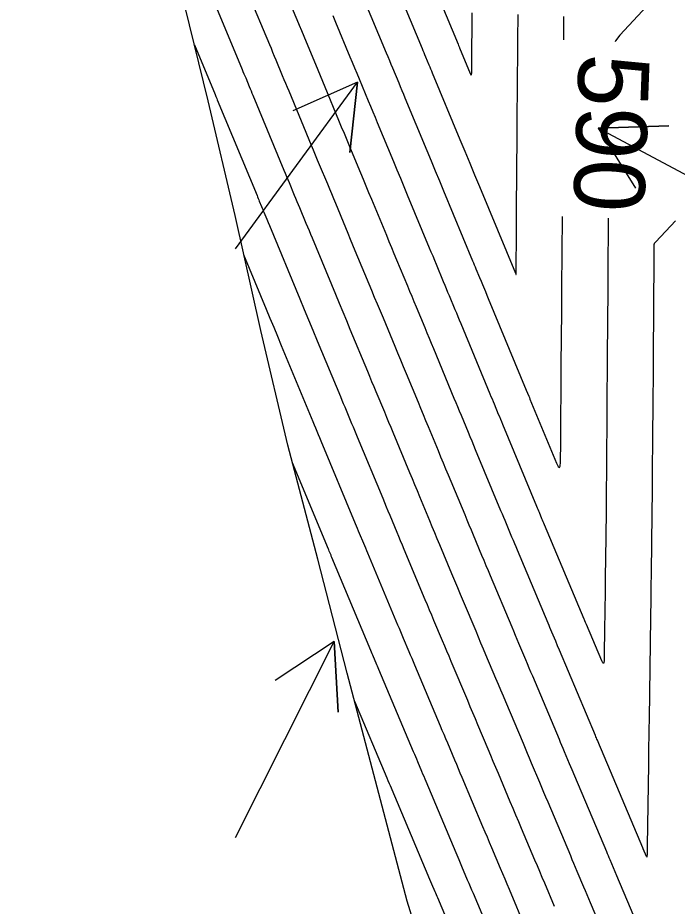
# Model space of a CAD drawing. Extents: x 954385 to 988206, y 1868364 to 1924553.
# Drawn here: x 957938.6 to 957994.6, y 1918863.1 to 1918938.6 of the extents above; entities that cross this region are included whole.
import ezdxf

# ---------------------------------------------------------------- set-up
doc = ezdxf.new("R2010")
doc.units = 0
for name, color, linetype in [('24', 7, 'Continuous'), ('26', 7, 'Continuous'), ('5', 7, 'Continuous'), ('6', 7, 'Continuous'), ('7', 7, 'Continuous')]:
    doc.layers.add(name, color=color, linetype=linetype)

msp = doc.modelspace()

# ---------------------------------------------------------------- linework, layer by layer
at = {"layer": '24'}
msp.add_lwpolyline([(957974.671, 1918853.956), (957971.691, 1918863.536), (957969.153, 1918873.215), (957966.605, 1918882.892), (957964.105, 1918892.58), (957961.58, 1918902.262), (957959.271, 1918911.992), (957957.104, 1918921.755), (957954.809, 1918931.489), (957952.428, 1918941.203), (957950.425, 1918951.002), (957949.07, 1918960.947), (957947.365, 1918970.813), (957946.225, 1918980.806), (957947.369, 1918991.311), (957948.976, 1919001.92), (957947.688, 1919008.805), (957946.681, 1919011.654), (957944.248, 1919021.357), (957948.184, 1919032.489), (957949.869, 1919043.116), (957945.982, 1919052.492), (957942.292, 1919061.913), (957938.649, 1919071.344)], dxfattribs=at)
at = {"layer": '26'}
for points in [[(957957.131, 1918918.928), (957967.485, 1918933.074), (957966.837, 1918927.109), (957967.485, 1918933.074), (957961.996, 1918930.653)], [(958007.131, 1918918.928), (957987.907, 1918929.179), (957993.904, 1918929.381), (957987.907, 1918929.179), (957991.081, 1918924.086)], [(957957.131, 1918868.928), (957965.513, 1918885.566), (957965.855, 1918879.576), (957965.513, 1918885.566), (957960.496, 1918882.276)]]:
    msp.add_lwpolyline(points, dxfattribs=at)
at = {"layer": '6'}
for points in [[(957992.035, 1918939.534), (957989.765, 1918937.088), (957989.381, 1918936.594), (957989.344, 1918936.521)], [(957988.775, 1918921.532), (957988.739, 1918916.732), (957988.736, 1918916.42), (957988.734, 1918916.107), (957988.731, 1918915.794), (957988.729, 1918915.482), (957988.686, 1918909.856), (957988.683, 1918909.443), (957988.678, 1918908.883), (957988.677, 1918908.703), (957988.675, 1918908.402), (957988.673, 1918908.222), (957988.664, 1918906.986), (957988.661, 1918906.534), (957988.658, 1918906.081), (957988.611, 1918899.574), (957988.605, 1918898.825), (957988.598, 1918898.077), (957988.591, 1918897.328), (957988.582, 1918896.58), (957988.532, 1918892.58), (957988.526, 1918892.09), (957988.52, 1918891.6), (957988.507, 1918890.619), (957988.504, 1918890.374), (957988.501, 1918890.129), (957988.498, 1918889.884), (957988.495, 1918889.638), (957988.479, 1918888.381), (957988.475, 1918888.09), (957988.472, 1918887.799), (957988.468, 1918887.508), (957988.463, 1918887.216), (957988.445, 1918885.933), (957988.441, 1918885.687), (957988.438, 1918885.441), (957988.434, 1918885.195), (957988.43, 1918884.949), (957988.416, 1918883.965), (957988.401, 1918883.778), (957988.363, 1918883.71), (957988.302, 1918883.759), (957988.218, 1918883.927), (957986.914, 1918887.025), (957986.848, 1918887.18), (957986.783, 1918887.335), (957986.75, 1918887.412), (957986.718, 1918887.49), (957983.36, 1918895.498), (957983.306, 1918895.627), (957983.253, 1918895.755), (957983.199, 1918895.883), (957983.145, 1918896.011), (957982.93, 1918896.524), (957982.877, 1918896.652), (957982.823, 1918896.78), (957982.77, 1918896.909), (957982.716, 1918897.037), (957979.821, 1918904.019), (957979.733, 1918904.233), (957979.644, 1918904.447), (957979.555, 1918904.661), (957979.467, 1918904.874), (957979.112, 1918905.729), (957979.023, 1918905.943), (957978.934, 1918906.156), (957978.846, 1918906.37), (957978.757, 1918906.584), (957976.274, 1918912.567), (957976.151, 1918912.864), (957976.028, 1918913.16), (957975.905, 1918913.457), (957975.782, 1918913.753), (957975.29, 1918914.939), (957975.167, 1918915.235), (957975.044, 1918915.532), (957974.921, 1918915.828), (957974.798, 1918916.124), (957974.183, 1918917.605), (957974.04, 1918917.951), (957973.896, 1918918.296), (957973.753, 1918918.642), (957973.609, 1918918.988), (957971.739, 1918923.496), (957971.446, 1918924.202), (957971.153, 1918924.908), (957970.86, 1918925.613), (957970.567, 1918926.319), (957969.196, 1918929.621), (957969.002, 1918930.087), (957968.809, 1918930.553), (957968.615, 1918931.019), (957968.422, 1918931.486), (957967.648, 1918933.351), (957967.454, 1918933.817), (957967.261, 1918934.283), (957967.067, 1918934.749), (957966.874, 1918935.215), (957965.648, 1918938.165), (957965.42, 1918938.714)], [(957981.788, 1918861.177), (957980.381, 1918864.515), (957980.194, 1918864.959), (957980.007, 1918865.402), (957979.82, 1918865.846), (957979.633, 1918866.29), (957978.884, 1918868.064), (957978.697, 1918868.508), (957978.51, 1918868.951), (957978.323, 1918869.395), (957978.136, 1918869.839), (957976.364, 1918874.039), (957976.211, 1918874.402), (957976.058, 1918874.765), (957975.905, 1918875.127), (957975.753, 1918875.49), (957975.141, 1918876.941), (957974.989, 1918877.304), (957974.836, 1918877.667), (957974.683, 1918878.03), (957974.53, 1918878.392), (957972.354, 1918883.558), (957972.234, 1918883.843), (957972.114, 1918884.128), (957971.995, 1918884.413), (957971.875, 1918884.699), (957971.397, 1918885.839), (957971.277, 1918886.124), (957971.158, 1918886.41), (957971.038, 1918886.695), (957970.919, 1918886.98), (957968.363, 1918893.079), (957968.276, 1918893.288), (957968.188, 1918893.496), (957968.102, 1918893.705), (957968.015, 1918893.914), (957967.668, 1918894.751), (957967.581, 1918894.96), (957967.495, 1918895.169), (957967.408, 1918895.378), (957967.321, 1918895.587), (957964.411, 1918902.598), (957964.297, 1918902.872), (957964.183, 1918903.146), (957963.955, 1918903.694), (957963.842, 1918903.968), (957963.728, 1918904.242), (957961.047, 1918910.703), (957960.727, 1918911.475), (957960.407, 1918912.247), (957960.086, 1918913.019), (957959.766, 1918913.791), (957957.844, 1918918.423)]]:
    msp.add_lwpolyline(points, dxfattribs=at)
at = {"layer": '7'}
for points in [[(957972.605, 1918944.525), (957976.022, 1918936.303), (957976.063, 1918936.203), (957976.136, 1918936.028), (957976.146, 1918936.003), (957977.047, 1918933.835), (957977.105, 1918933.717), (957977.147, 1918933.682), (957977.173, 1918933.73), (957977.182, 1918933.861), (957977.188, 1918934.554), (957977.189, 1918934.728), (957977.191, 1918934.901), (957977.192, 1918935.074), (957977.193, 1918935.247), (957977.2, 1918936.111), (957977.202, 1918936.312), (957977.204, 1918936.514), (957977.205, 1918936.716), (957977.207, 1918936.917), (957977.225, 1918938.972)], [(957970.286, 1918942.405), (957972.972, 1918935.941), (957973.044, 1918935.769), (957973.115, 1918935.597), (957973.187, 1918935.424), (957973.258, 1918935.252), (957973.544, 1918934.564), (957973.615, 1918934.392), (957973.686, 1918934.22), (957973.758, 1918934.048), (957973.829, 1918933.876), (957976.178, 1918928.221), (957976.593, 1918927.221), (957977.008, 1918926.222), (957977.423, 1918925.222), (957977.838, 1918924.222), (957980.895, 1918916.854), (957980.935, 1918916.759), (957980.939, 1918916.749), (957980.943, 1918916.746), (957980.945, 1918916.75), (957980.946, 1918916.761), (957980.947, 1918916.887), (957980.975, 1918920.531), (957980.979, 1918921.035), (957980.982, 1918921.538), (957980.986, 1918922.042), (957980.99, 1918922.546), (957981.01, 1918925.179), (957981.013, 1918925.568), (957981.016, 1918925.957), (957981.022, 1918926.734), (957981.023, 1918926.929), (957981.025, 1918927.123), (957981.026, 1918927.317), (957981.028, 1918927.512), (957981.046, 1918929.825), (957981.095, 1918935.937), (957981.101, 1918936.663), (957981.107, 1918937.39), (957981.113, 1918938.116), (957981.119, 1918938.843)], [(957994.466, 1918921.316), (957992.817, 1918919.536), (957992.69, 1918919.399), (957992.675, 1918919.379), (957992.663, 1918919.357), (957992.656, 1918919.333), (957992.654, 1918919.307), (957992.605, 1918912.758), (957992.602, 1918912.404), (957992.599, 1918912.05), (957992.597, 1918911.696), (957992.594, 1918911.342), (957992.583, 1918909.926), (957992.58, 1918909.572), (957992.578, 1918909.218), (957992.575, 1918908.864), (957992.572, 1918908.51), (957992.552, 1918905.79), (957992.548, 1918905.219), (957992.544, 1918904.648), (957992.54, 1918904.076), (957992.536, 1918903.505), (957992.506, 1918899.377), (957992.505, 1918899.164), (957992.503, 1918898.952), (957992.501, 1918898.74), (957992.498, 1918898.528), (957992.442, 1918894.038), (957992.435, 1918893.502), (957992.429, 1918892.966), (957992.422, 1918892.43), (957992.415, 1918891.894), (957992.388, 1918889.747), (957992.382, 1918889.211), (957992.375, 1918888.675), (957992.367, 1918888.138), (957992.36, 1918887.602), (957992.236, 1918879.048), (957992.231, 1918878.72), (957992.226, 1918878.393), (957992.221, 1918878.066), (957992.216, 1918877.739), (957992.196, 1918876.43), (957992.191, 1918876.102), (957992.187, 1918875.775), (957992.182, 1918875.448), (957992.177, 1918875.121), (957992.073, 1918868.231), (957992.071, 1918868.11), (957992.069, 1918867.988), (957992.064, 1918867.674), (957992.062, 1918867.522), (957992.059, 1918867.32), (957992.056, 1918867.281), (957992.048, 1918867.267), (957992.036, 1918867.277), (957992.018, 1918867.312), (957991.737, 1918867.979), (957991.709, 1918868.047), (957988.197, 1918876.372), (957988.025, 1918876.78), (957987.853, 1918877.188), (957987.81, 1918877.29), (957987.767, 1918877.392), (957987.724, 1918877.494), (957987.681, 1918877.596), (957984.634, 1918884.83), (957984.472, 1918885.215), (957984.31, 1918885.6), (957983.985, 1918886.371), (957983.904, 1918886.563), (957983.823, 1918886.756), (957983.742, 1918886.948), (957983.662, 1918887.141), (957981.068, 1918893.326), (957980.951, 1918893.606), (957980.834, 1918893.886), (957980.716, 1918894.165), (957980.599, 1918894.445), (957980.13, 1918895.564), (957980.013, 1918895.844), (957979.896, 1918896.124), (957979.78, 1918896.404), (957979.664, 1918896.684), (957977.516, 1918901.864), (957977.365, 1918902.228), (957977.214, 1918902.591), (957977.063, 1918902.955), (957976.912, 1918903.318), (957976.309, 1918904.772), (957976.158, 1918905.136), (957976.007, 1918905.499), (957975.856, 1918905.863), (957975.705, 1918906.226), (957973.959, 1918910.434), (957973.775, 1918910.878), (957973.59, 1918911.322), (957973.406, 1918911.766), (957973.222, 1918912.21), (957972.485, 1918913.986), (957972.301, 1918914.431), (957972.116, 1918914.875), (957971.932, 1918915.319), (957971.748, 1918915.763), (957970.827, 1918917.981), (957970.612, 1918918.499), (957970.397, 1918919.017), (957970.182, 1918919.535), (957969.967, 1918920.053), (957968.689, 1918923.133), (957968.458, 1918923.692), (957968.226, 1918924.251), (957967.994, 1918924.809), (957967.762, 1918925.368), (957966.834, 1918927.603), (957966.602, 1918928.161), (957966.37, 1918928.72), (957966.138, 1918929.279), (957965.906, 1918929.837), (957964.729, 1918932.674), (957964.531, 1918933.15), (957964.334, 1918933.626), (957964.136, 1918934.102), (957963.938, 1918934.579), (957963.147, 1918936.483), (957962.949, 1918936.96), (957962.751, 1918937.436), (957962.553, 1918937.912), (957962.355, 1918938.388), (957961.017, 1918941.609)], [(957992.669, 1918858.163), (957989.507, 1918865.668), (957989.363, 1918866.009), (957989.22, 1918866.35), (957988.932, 1918867.032), (957988.86, 1918867.202), (957988.789, 1918867.373), (957988.717, 1918867.543), (957988.645, 1918867.714), (957985.928, 1918874.154), (957985.71, 1918874.67), (957985.493, 1918875.186), (957985.057, 1918876.219), (957984.948, 1918876.477), (957984.84, 1918876.735), (957984.731, 1918876.993), (957984.622, 1918877.252), (957982.355, 1918882.635), (957982.209, 1918882.982), (957982.063, 1918883.328), (957981.917, 1918883.674), (957981.771, 1918884.021), (957981.188, 1918885.406), (957981.042, 1918885.752), (957980.896, 1918886.099), (957980.751, 1918886.445), (957980.605, 1918886.792), (957978.776, 1918891.154), (957978.595, 1918891.585), (957978.415, 1918892.017), (957978.234, 1918892.448), (957978.053, 1918892.879), (957977.33, 1918894.604), (957977.15, 1918895.036), (957976.97, 1918895.467), (957976.79, 1918895.899), (957976.611, 1918896.331), (957975.21, 1918899.709), (957974.997, 1918900.222), (957974.784, 1918900.736), (957974.571, 1918901.249), (957974.358, 1918901.762), (957973.506, 1918903.816), (957973.292, 1918904.329), (957973.079, 1918904.842), (957972.866, 1918905.356), (957972.653, 1918905.869), (957971.635, 1918908.323), (957971.394, 1918908.903), (957971.153, 1918909.483), (957970.913, 1918910.064), (957970.672, 1918910.644), (957969.68, 1918913.034), (957969.434, 1918913.626), (957969.189, 1918914.218), (957968.943, 1918914.809), (957968.698, 1918915.401), (957967.298, 1918918.774), (957967.098, 1918919.256), (957966.898, 1918919.738), (957966.698, 1918920.22), (957966.498, 1918920.702), (957965.64, 1918922.771), (957965.469, 1918923.182), (957965.298, 1918923.594), (957965.127, 1918924.005), (957964.956, 1918924.417), (957964.273, 1918926.063), (957964.102, 1918926.475), (957963.931, 1918926.887), (957963.76, 1918927.298), (957963.589, 1918927.71), (957961.681, 1918932.31), (957961.544, 1918932.639), (957961.407, 1918932.969), (957961.27, 1918933.299), (957961.133, 1918933.629), (957960.584, 1918934.949), (957960.447, 1918935.278), (957960.31, 1918935.608), (957960.173, 1918935.938), (957960.036, 1918936.268), (957958.212, 1918940.66)], [(957967.967, 1918940.285), (957969.923, 1918935.578), (957970.056, 1918935.259), (957970.188, 1918934.94), (957970.321, 1918934.621), (957970.453, 1918934.301), (957970.983, 1918933.025), (957971.115, 1918932.706), (957971.248, 1918932.387), (957971.38, 1918932.068), (957971.513, 1918931.748), (957973.373, 1918927.27), (957973.727, 1918926.417), (957974.081, 1918925.565), (957974.435, 1918924.712), (957974.789, 1918923.859), (957977.251, 1918917.923), (957977.323, 1918917.749), (957977.395, 1918917.576), (957977.467, 1918917.402), (957977.539, 1918917.229), (957977.848, 1918916.486), (957977.971, 1918916.188), (957978.095, 1918915.891), (957978.341, 1918915.296), (957978.465, 1918914.999), (957978.588, 1918914.701), (957981.809, 1918906.941), (957981.915, 1918906.685), (957982.021, 1918906.43), (957982.074, 1918906.302), (957982.127, 1918906.175), (957984.383, 1918900.733), (957984.53, 1918900.435), (957984.636, 1918900.346), (957984.7, 1918900.468), (957984.724, 1918900.799), (957984.736, 1918902.545), (957984.739, 1918902.981), (957984.742, 1918903.417), (957984.746, 1918903.853), (957984.749, 1918904.29), (957984.77, 1918907.139), (957984.771, 1918907.303), (957984.772, 1918907.466), (957984.773, 1918907.63), (957984.775, 1918907.793), (957984.78, 1918908.447), (957984.782, 1918908.774), (957984.785, 1918909.101), (957984.818, 1918913.617), (957984.822, 1918914.028), (957984.825, 1918914.44), (957984.828, 1918914.852), (957984.831, 1918915.263), (957984.844, 1918916.909), (957984.847, 1918917.321), (957984.85, 1918917.732), (957984.853, 1918918.144), (957984.856, 1918918.555), (957984.88, 1918921.679)], [(957989.599, 1918857.846), (957987.263, 1918863.391), (957987.123, 1918863.724), (957986.982, 1918864.056), (957986.842, 1918864.389), (957986.702, 1918864.721), (957986.142, 1918866.051), (957986.002, 1918866.384), (957985.861, 1918866.716), (957985.721, 1918867.048), (957985.581, 1918867.381), (957983.66, 1918871.935), (957983.485, 1918872.35), (957983.31, 1918872.764), (957983.136, 1918873.178), (957982.961, 1918873.592), (957982.262, 1918875.25), (957982.087, 1918875.664), (957981.912, 1918876.078), (957981.738, 1918876.493), (957981.563, 1918876.907), (957980.075, 1918880.441), (957979.865, 1918880.941), (957979.654, 1918881.441), (957979.443, 1918881.941), (957979.233, 1918882.441), (957978.39, 1918884.442), (957978.179, 1918884.942), (957977.969, 1918885.442), (957977.759, 1918885.942), (957977.549, 1918886.443), (957976.484, 1918888.982), (957976.24, 1918889.565), (957975.996, 1918890.148), (957975.751, 1918890.73), (957975.507, 1918891.313), (957974.468, 1918893.794), (957974.255, 1918894.302), (957974.043, 1918894.81), (957973.831, 1918895.319), (957973.62, 1918895.827), (957972.776, 1918897.862), (957972.565, 1918898.371), (957972.354, 1918898.88), (957972.143, 1918899.389), (957971.932, 1918899.897), (957970.511, 1918903.321), (957970.331, 1918903.753), (957970.152, 1918904.185), (957969.972, 1918904.618), (957969.793, 1918905.05), (957969.075, 1918906.78), (957968.896, 1918907.213), (957968.716, 1918907.645), (957968.537, 1918908.077), (957968.357, 1918908.51), (957966.875, 1918912.082), (957966.568, 1918912.821), (957966.262, 1918913.561), (957965.955, 1918914.3), (957965.648, 1918915.04), (957963.656, 1918919.839), (957963.527, 1918920.149), (957963.399, 1918920.458), (957963.27, 1918920.768), (957963.142, 1918921.078), (957962.59, 1918922.408), (957962.48, 1918922.672), (957962.371, 1918922.937), (957962.261, 1918923.201), (957962.151, 1918923.466), (957961.711, 1918924.524), (957961.602, 1918924.789), (957961.492, 1918925.053), (957961.382, 1918925.318), (957961.272, 1918925.582), (957958.632, 1918931.946), (957958.556, 1918932.129), (957958.48, 1918932.313), (957958.403, 1918932.496), (957958.327, 1918932.68), (957958.022, 1918933.414), (957957.946, 1918933.597), (957957.87, 1918933.781), (957957.793, 1918933.964), (957957.717, 1918934.148), (957955.406, 1918939.71)], [(957984.997, 1918936.686), (957985.003, 1918937.44), (957985.007, 1918937.853), (957985.01, 1918938.266), (957985.013, 1918938.679)], [(957953.639, 1918936.261), (957955.398, 1918932.028), (957955.46, 1918931.879), (957955.537, 1918931.693), (957955.583, 1918931.581), (957958.955, 1918923.455), (957959.004, 1918923.337), (957959.053, 1918923.22), (957959.102, 1918923.102), (957959.15, 1918922.985), (957959.346, 1918922.515), (957959.394, 1918922.397), (957959.443, 1918922.28), (957959.492, 1918922.162), (957959.541, 1918922.045), (957959.786, 1918921.454), (957959.9, 1918921.179), (957960.014, 1918920.904), (957962.598, 1918914.678), (957962.966, 1918913.791), (957963.334, 1918912.904), (957963.702, 1918912.017), (957964.07, 1918911.129), (957966.043, 1918906.376), (957966.161, 1918906.091), (957966.279, 1918905.807), (957966.397, 1918905.522), (957966.515, 1918905.237), (957966.988, 1918904.098), (957967.106, 1918903.813), (957967.224, 1918903.529), (957967.342, 1918903.244), (957967.461, 1918902.959), (957969.627, 1918897.742), (957969.776, 1918897.383), (957969.924, 1918897.024), (957970.073, 1918896.665), (957970.222, 1918896.306), (957970.817, 1918894.871), (957970.966, 1918894.512), (957971.116, 1918894.153), (957971.265, 1918893.795), (957971.415, 1918893.436), (957973.211, 1918889.152), (957973.394, 1918888.715), (957973.577, 1918888.279), (957973.76, 1918887.842), (957973.943, 1918887.405), (957974.675, 1918885.658), (957974.858, 1918885.222), (957975.042, 1918884.785), (957975.225, 1918884.349), (957975.409, 1918883.912), (957976.81, 1918880.587), (957977.027, 1918880.07), (957977.245, 1918879.554), (957977.462, 1918879.037), (957977.68, 1918878.521), (957978.55, 1918876.455), (957978.768, 1918875.938), (957978.985, 1918875.421), (957979.203, 1918874.905), (957979.421, 1918874.389), (957980.429, 1918871.999), (957980.67, 1918871.428), (957980.91, 1918870.858), (957981.151, 1918870.287), (957981.391, 1918869.717), (957982.517, 1918867.048), (957982.726, 1918866.554), (957982.934, 1918866.059), (957983.143, 1918865.565), (957983.351, 1918865.07), (957984.185, 1918863.092)], [(957979.543, 1918858.9), (957977.322, 1918864.17), (957977.201, 1918864.458), (957977.08, 1918864.745), (957976.959, 1918865.033), (957976.837, 1918865.32), (957976.352, 1918866.47), (957976.11, 1918867.045), (957975.867, 1918867.62), (957973.307, 1918873.69), (957973.219, 1918873.899), (957973.131, 1918874.108), (957973.043, 1918874.317), (957972.955, 1918874.526), (957972.603, 1918875.362), (957972.515, 1918875.571), (957972.427, 1918875.78), (957972.339, 1918875.989), (957972.251, 1918876.198), (957969.299, 1918883.204), (957969.243, 1918883.338), (957969.187, 1918883.471), (957969.131, 1918883.605), (957969.075, 1918883.739), (957968.851, 1918884.273), (957968.795, 1918884.407), (957968.739, 1918884.541), (957968.683, 1918884.674), (957968.627, 1918884.808), (957965.311, 1918892.721), (957965.286, 1918892.78), (957965.261, 1918892.839), (957965.237, 1918892.899), (957965.212, 1918892.958), (957965.089, 1918893.254), (957965.04, 1918893.372), (957965.016, 1918893.431), (957961.969, 1918900.769)], [(957967.235, 1918880.498), (957969.971, 1918874.003), (957970.064, 1918873.782), (957970.181, 1918873.506), (957970.227, 1918873.396), (957970.25, 1918873.34), (957973.599, 1918865.402), (957973.765, 1918865.008), (957974.042, 1918864.351), (957974.097, 1918864.22), (957974.153, 1918864.088), (957974.208, 1918863.957), (957974.263, 1918863.826), (957977.299, 1918856.623)]]:
    msp.add_lwpolyline(points, dxfattribs=at)

# ---------------------------------------------------------------- texts
at = {"layer": '5'}
msp.add_text('590', height=6, rotation=267.83157, dxfattribs=at).set_placement((957986.304, 1918935.564))

doc.saveas('drawing.dxf')
